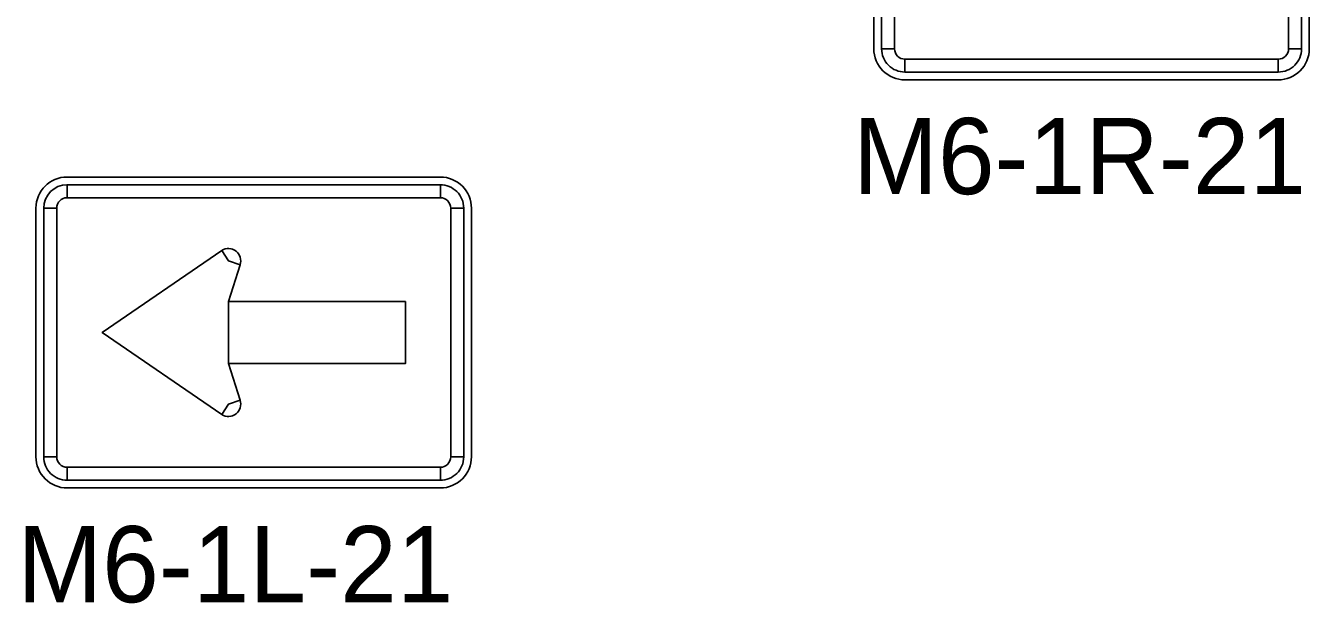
# Model space of a CAD drawing. Extents: x 2025369 to 2161369, y 549489 to 637489.
# Drawn here: x 2119659 to 2129092, y 602397 to 606644 of the extents above; entities that cross this region are included whole.
import ezdxf

# ---------------------------------------------------------------- set-up
doc = ezdxf.new("R2010")
doc.units = 0
doc.layers.add('SH_Text', color=7, linetype='Continuous')
doc.layers.add('SN_P_Signs', color=7, linetype='Continuous')

msp = doc.modelspace()

# ---------------------------------------------------------------- linework, layer by layer
at = {"layer": 'SN_P_Signs'}
for p, q in [((2125891.9, 608302.8), (2125891.9, 606474)), ((2129092.3, 606474), (2129092.3, 608302.8)), ((2126044.3, 606474), (2125949.1, 606474)), ((2126120.5, 606302.6), (2126120.5, 606397.8)), ((2128863.7, 606397.8), (2128863.7, 606302.6)), ((2129035.2, 606474), (2128939.9, 606474)), ((2126120.5, 606245.4), (2128863.7, 606245.4)), ((2122706.1, 605531.4), (2119962.9, 605531.4)), ((2119962.9, 605379), (2119962.9, 605474.3)), ((2122706.1, 605474.3), (2122706.1, 605379)), ((2119734.3, 605302.8), (2119734.3, 603474)), ((2119791.5, 605302.8), (2119886.7, 605302.8)), ((2122782.3, 605302.8), (2122877.6, 605302.8)), ((2122934.7, 603474), (2122934.7, 605302.8)), ((2121099.5, 604991.6), (2121148.2, 604914.2)), ((2121148.2, 604914.2), (2121235.2, 604886.1)), ((2121148.2, 603862.6), (2121099.5, 603785.2)), ((2121235.2, 603890.8), (2121148.2, 603862.6)), ((2119886.7, 603474), (2119791.5, 603474)), ((2122877.6, 603474), (2122782.3, 603474)), ((2119962.9, 603302.6), (2119962.9, 603397.8)), ((2122706.1, 603397.8), (2122706.1, 603302.6)), ((2119962.9, 603245.4), (2122706.1, 603245.4))]:
    msp.add_line(p, q, dxfattribs=at)
for points in [[(2125949.1, 608302.8), (2125949.1, 606474), (2126044.3, 606474), (2126044.3, 608302.8), (2125949.1, 608302.8), (2125949.1, 608302.8)], [(2129035.2, 606474), (2129035.2, 608302.8), (2128939.9, 608302.8), (2128939.9, 606474), (2129035.2, 606474), (2129035.2, 606474)], [(2126120.5, 606302.6), (2128863.7, 606302.6), (2128863.7, 606397.8), (2126120.5, 606397.8), (2126120.5, 606302.6), (2126120.5, 606302.6)], [(2122706.1, 605474.3), (2119962.9, 605474.3), (2119962.9, 605379), (2122706.1, 605379), (2122706.1, 605474.3), (2122706.1, 605474.3)], [(2119791.5, 605302.8), (2119791.5, 603474), (2119886.7, 603474), (2119886.7, 605302.8), (2119791.5, 605302.8), (2119791.5, 605302.8)], [(2122877.6, 603474), (2122877.6, 605302.8), (2122782.3, 605302.8), (2122782.3, 603474), (2122877.6, 603474), (2122877.6, 603474)], [(2120220.1, 604388.4), (2121099.5, 603785.2), (2121148.2, 603862.6), (2121235.2, 603890.8), (2121148.2, 604159.8), (2121148.2, 604617), (2121235.2, 604886.1), (2121148.2, 604914.2), (2121099.5, 604991.6), (2120220.1, 604388.4), (2120220.1, 604388.4)], [(2122448.9, 604617), (2122448.9, 604159.8), (2121148.2, 604159.8), (2121148.2, 604617), (2122448.9, 604617), (2122448.9, 604617)], [(2119962.9, 603302.6), (2122706.1, 603302.6), (2122706.1, 603397.8), (2119962.9, 603397.8), (2119962.9, 603302.6), (2119962.9, 603302.6)]]:
    msp.add_lwpolyline(points, close=True, dxfattribs=at)
for centre, radius, start, end in [((2126120.5, 606474), 228.6, 179.99985, 270.00006), ((2126120.5, 606474), 171.5, 179.99985, 270.00006), ((2126120.5, 606474), 76.2, 179.99985, 270.00006), ((2128863.7, 606474), 228.6, 270.00006, 0.00027), ((2128863.7, 606474), 171.5, 270.00006, 0.00027), ((2128863.7, 606474), 76.2, 270.00006, 0.00027), ((2119962.9, 605302.8), 228.6, 90.00021, 179.99985), ((2119962.9, 605302.8), 171.5, 90.00021, 179.99985), ((2122706.1, 605302.8), 228.6, 0, 90.00021), ((2122706.1, 605302.8), 171.5, 0, 90.00021), ((2119962.9, 605302.8), 76.2, 90.00021, 179.99985), ((2122706.1, 605302.8), 76.2, 0, 90.00021), ((2121148.2, 604914.2), 91.4, 342.07987, 122.1457), ((2121148.2, 603862.6), 91.4, 237.85426, 17.9201), ((2119962.9, 603474), 228.6, 179.99985, 270.00006), ((2119962.9, 603474), 171.5, 179.99985, 270.00006), ((2119962.9, 603474), 76.2, 179.99985, 270.00006), ((2122706.1, 603474), 228.6, 270.00006, 0.00027), ((2122706.1, 603474), 171.5, 270.00006, 0.00027), ((2122706.1, 603474), 76.2, 270.00006, 0.00027)]:
    msp.add_arc(centre, radius, start, end, dxfattribs=at)

# ---------------------------------------------------------------- texts
at = {"layer": 'SH_Text'}
for s, p in [('M6-1R-21', (2125739.3, 605405.4)), ('M6-1L-21', (2119597.2, 602405.4))]:
    msp.add_text(s, height=560, dxfattribs=at).set_placement(p)

doc.saveas('drawing.dxf')
